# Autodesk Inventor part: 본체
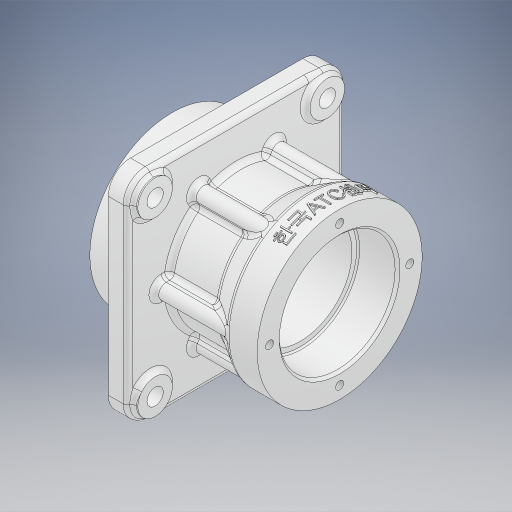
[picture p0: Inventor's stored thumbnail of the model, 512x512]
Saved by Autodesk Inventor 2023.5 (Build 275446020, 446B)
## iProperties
Created: 2025-08
Part Number: 본체
Material: 알루미늄 6061
Document SubType Name: Modeling
Designer: 1강의실14
Density: 2.7 g/cm^3
Appearance: 알루미늄 - 평지
Mass: 400.823 g
Surface Area: 396.935 cm^2
Volume: 148.453 cm^3
Author: 1강의실14
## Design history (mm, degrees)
sketch "스케치1"
  geometry: C1 r 27.5 at (0, 0); 1 further point
  constraints: 1 centre point, 1 coincident
  dimensions: "d0" = 55 diameter of C1
extrude "돌출1" new body sketch "스케치1" stored distance "d1" = 68; taper "d2" = 0 deg
sketch "스케치2"
  geometry: C1 r 33.5 at (0, 0); 1 further point
  constraints: 1 centre point, 1 coincident
  dimensions: "d3" = 67 diameter of C1
extrude "돌출2" join sketch "스케치2" distance "d4" = 13; taper "d5" = 0 deg
sketch "스케치3"
  geometry: C1 r 38.5 at (0, 0); 1 further point
  constraints: 1 centre point, 1 coincident
  dimensions: "d6" = 77 diameter of C1
extrude "돌출3" join sketch "스케치3" distance "d7" = 5; taper "d8" = 0 deg
sketch "스케치4"
  geometry: L1 (-35, -44)-(35, -44); L2 (44, -35)-(44, 35); L3 (35, 44)-(-35, 44); L4 (-44, 35)-(-44, -35); L5 (-44, -44)-(44, 44); L6 (44, -44)-(-44, 44); A1 r 9 centre (-35, 35) between (-35, 44) and (-44, 35); A2 r 9 centre (-35, -35) between (-44, -35) and (-35, -44); A3 r 9 centre (35, -35) between (35, -44) and (44, -35); A4 r 9 centre (35, 35) between (44, 35) and (35, 44); 1 further point
  constraints: 12 end point, 8 point on circle, 8 point on line, 8 tangent, 4 centre point, 3 equal radius, 2 midpoint, 2 parallel, 1 horizontal, 1 perpendicular
  dimensions: "d9" = 88 distance of L6.start L5.end; "d10" = 88 distance of L5.end L6.end; "d11" = 9 radius of A1
extrude "돌출4" join sketch "스케치4" distance "d12" = 8; taper "d13" = 0 deg
sketch "스케치5"
  geometry: C1 r 33.5 at (0, 0); 1 further point
  constraints: 1 centre point, 1 coincident
  dimensions: "d14" = 67 diameter of C1
extrude "돌출5" join sketch "스케치5" distance "d15" = 12; taper "d16" = 0 deg
sketch "스케치6"
  geometry: L1 (34, 33.5)-(22, 33.5) reference; L2 (22, 33.5)-(12, 27.5); L3 (-8, 27.5)-(22, 27.5) reference; L4 (12, 27.5)-(12, 0); L5 (22, 33.5)-(22, 0); L6 (22, 33.5)-(22, -33.5) reference; L7 (12, 0)-(22, 0); L8 (34, -33.5)-(34, 33.5) reference; 3 further points
  constraints: 8 end point, 2 midpoint, 2 point on line, 1 horizontal alignment, 1 perpendicular, 1 vertical
  dimensions: "d83" = 22 distance between parallel lines of L8 L4
revolve "회전1" sketch "스케치6" stored, may be unused: angle "d18" = 90 deg
sketch "스케치7"
  geometry: L1 (-34, 33.5)-(-34, -33.5) reference; L2 (-34, 0)-(34, 0); L3 (34, -33.5)-(34, 33.5) reference; L4 (34, 0)-(34, 23.5); L5 (34, 23.5)-(18.6, 23.5); L6 (18, 22.9)-(18, 21); L7 (18, 21)-(-18, 21); L8 (-18, 21)-(-18, 22.9); L9 (-18.6, 23.5)-(-34, 23.5); L10 (-34, 23.5)-(-34, 0); A1 r 0.6 centre (18.6, 22.9) between (18.6, 23.5) and (18, 22.9); A2 r 0.6 centre (-18.6, 22.9) between (-18, 22.9) and (-18.6, 23.5); 3 further points
  constraints: 16 end point, 6 point on line, 4 perpendicular, 4 point on circle, 4 tangent, 2 centre point, 2 midpoint, 1 collinear, 1 equal radius, 1 vertical
  dimensions: "d19" = 47 diameter of L5 L2; "d20" = 16 distance of L4.end point (18, 23.5); "d21" = 16 distance of point (-18, 23.5) L9.end; "d22" = 42 diameter of L7 L2; "d76" = 0.6 radius of A1
revolve "회전2" sketch "스케치7" stored, may be unused: angle "d23" = 90 deg
sketch "스케치8"
  geometry: L1 (44, -35)-(44, 35) reference; L2 (35, 44)-(-35, 44) reference; L3 (-44, 35)-(-44, -35) reference; L4 (-35, -44)-(35, -44) reference; C1 r 27.5 at (0, 0) reference; C2 r 7 at (-35, 35); C3 r 3.3 at (-35, 35); C4 r 7 at (35, 35); C5 r 3.3 at (35, 35); C6 r 7 at (-35, -35); C7 r 3.3 at (-35, -35); C8 r 7 at (35, -35); C9 r 3.3 at (35, -35); A1 r 9 centre (35, -35) between (35, -44) and (44, -35) reference; A2 r 9 centre (35, 35) between (44, 35) and (35, 44) reference; A3 r 9 centre (-35, 35) between (-35, 44) and (-44, 35) reference; A4 r 9 centre (-35, -35) between (-44, -35) and (-35, -44) reference; 1 further point
  constraints: 8 centre point, 8 coincident
  dimensions: "d24" = 14 diameter of C2; "d25" = 6.6 diameter of C3; "d26" = 14 diameter of C4; "d27" = 6.6 diameter of C5; "d28" = 14 diameter of C6; "d29" = 6.6 diameter of C7; "d30" = 14 diameter of C8; "d31" = 6.6 diameter of C9
  node "투영된 루프1"
extrude "돌출6" join sketch "스케치8" distance "d32" = 2; taper "d33" = 0 deg
extrude "돌출7" cut sketch "스케치8" stored distance "d34" = 2; taper "d35" = 0 deg
sketch "스케치9"
  geometry: L1 (-15.25, 26.414)-(0, 0); L2 (-17.848, 24.914)-(-2.598, -1.5); L3 (2.598, 1.5)-(-12.652, 27.914); L4 (0, 0)-(0, 44); L5 (35, 44)-(-35, 44) reference; C1 r 23.5 at (0, 0) reference; C2 r 33.5 at (0, 0) reference; C3 r 23.5 at (0, 0) reference; C4 r 23.5 at (0, 0) reference; C5 r 23.5 at (0, 0); A1 r 3 centre (-15.25, 26.414) between (-12.652, 27.914) and (-17.848, 24.914); A2 r 3 centre (0, 0) between (-2.598, -1.5) and (2.598, 1.5); 4 further points
  constraints: 10 end point, 5 tangent, 4 point on circle, 3 centre point, 2 coincident, 2 midpoint, 1 concentric, 1 parallel
  dimensions: "d36" = 6 distance between parallel lines of L2 L3; "d37" = 30 deg angle of L4 L1
extrude "돌출8" join sketch "스케치9" stored distance "d38" = 10; taper "d39" = 0 deg
sketch "스케치10"
  geometry: L1 (-34, 33.5)-(-34, -33.5) reference; 3 further points
  constraints: 1 horizontal alignment, 1 midpoint, 1 other
  dimensions: "d43" = 6 distance from line of point (-28, 0) L1
feature "엠보싱1" sketch "스케치10" dims "d9" = 88, "d10" = 88, "d11" = 9, "d44" = 0.5, "d45" = 0
fillet "모깎기2" dims "d47" = 2
chamfer "모따기1" distance "d48" = 1; stored, may be unused: second distance "d49" = 2, angle "d50" = 45 deg
sketch "스케치11" dims "d58" = 57
  geometry: 3 further points
  constraints: 2 vertical alignment, 1 coincident, 2 other
hole "구멍1" sketch "스케치11" at (0, 28.5) diameter "d51" = 3.242; stored, may be unused: countersink angle "d55" = 90 deg, drill point angle "d57" = 118 deg; dims "d52" = 8, "d53" = 15, "d54" = 4, "d56" = 10
sketch "스케치12" dims "d69" = 57
  geometry: 3 further points
  constraints: 2 vertical alignment, 1 coincident, 2 other
hole "구멍2" sketch "스케치12" at (0, 28.5) diameter "d62" = 3.242; stored, may be unused: countersink angle "d66" = 90 deg, drill point angle "d68" = 118 deg; dims "d63" = 8, "d64" = 4, "d65" = 2, "d67" = 10
fillet "모깎기3" dims "d73" = 2
fillet "모깎기6" dims "d77" = 2
fillet "모깎기7" dims "d78" = 2
chamfer "모따기2" distance "d79" = 1; stored, may be unused: second distance "d80" = 2, angle "d81" = 45 deg
feature "ж耀и耀к耀м耀о耀р耀т耀ф耀" dims "d0" = 55, "d1" = 68, "d2" = 0, "d3" = 67, "d4" = 13, "d5" = 0, "d6" = 77, "d7" = 5, "d8" = 0, "d9" = 88, "d10" = 88, "d11" = 9, "d12" = 8, "d13" = 0, "d14" = 67, "d15" = 12, "d16" = 0, "d18" = 90 deg, "d19" = 47, "d20" = 16, "d21" = 16, "d22" = 42, "d23" = 90 deg, "d24" = 14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
node "솔리드1"
pattern_circular "원형 패턴1" dims angle "d41" = 360 deg
pattern_circular "원형 패턴2" dims angle "d60" = 360 deg
pattern_circular "원형 패턴3" dims angle "d71" = 360 deg
node "투영된 루프2"
feature "A9D066F2-1C7D-4E18-AEED-F7BC21143FA4" dims "d51" = 3.242, "d52" = 8, "d53" = 15, "d54" = 4, "d55" = 90 deg, "d56" = 10, "d57" = 118 deg
